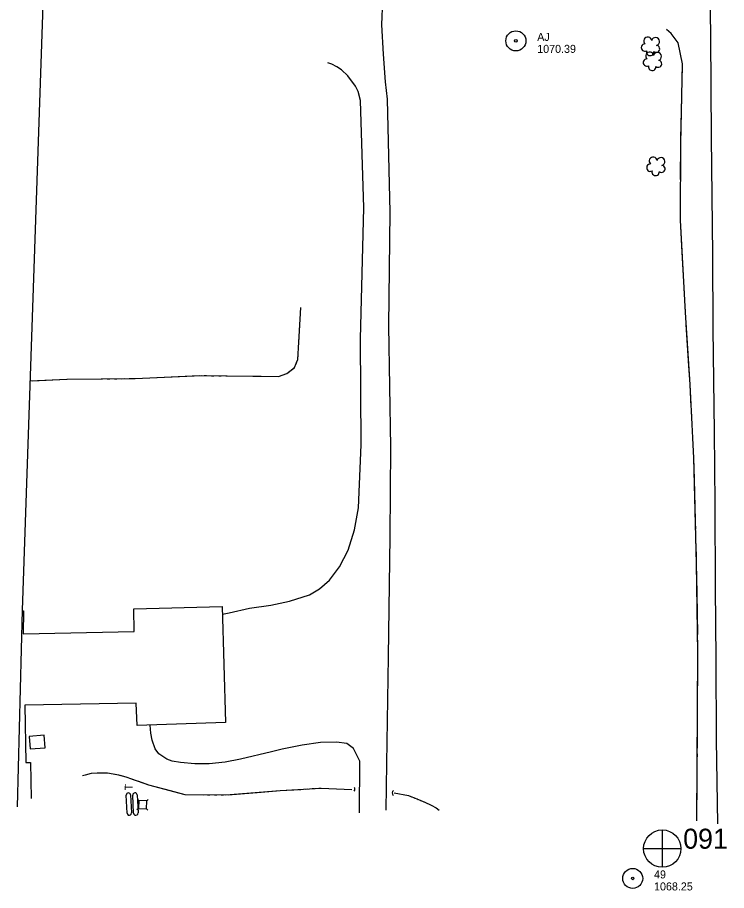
# Model space of a CAD drawing. Extents: x 296471 to 298892, y 33801 to 34997.
# Drawn here: x 297188 to 297719, y 33801 to 34456 of the extents above; entities that cross this region are included whole.
import ezdxf

# ---------------------------------------------------------------- set-up
doc = ezdxf.new("R2010")
doc.units = 0
for name, color, linetype in [('Level 11', 7, 'Continuous'), ('Level 12', 7, 'Continuous'), ('Level 15', 7, 'Continuous'), ('Level 17', 7, 'Continuous'), ('Level 18', 7, 'Continuous'), ('Level 19', 7, 'Continuous'), ('Level 21', 7, 'Continuous'), ('Level 4', 7, 'Continuous'), ('Level 6', 7, 'Continuous')]:
    doc.layers.add(name, color=color, linetype=linetype)

msp = doc.modelspace()

# ---------------------------------------------------------------- linework, layer by layer
at = {"layer": 'Level 11'}
msp.add_lwpolyline([(297712.34, 33851.57), (297711.29, 33914.53), (297711.16, 33974.94), (297710.5, 34028.32), (297710.34, 34091.16), (297709.89, 34145.17), (297708.94, 34222.49), (297708.52, 34278.1), (297707.52, 34365.88), (297707.09, 34441.48), (297706.15, 34514.1), (297705.99, 34583.52), (297706.04, 34650.6), (297705.21, 34744.77), (297704.07, 34846.29), (297703.4, 34892.56)], dxfattribs=at)
at = {"layer": 'Level 12'}
for p, q in [((297269.85, 33859.52), (297269.23, 33873)), ((297272.52, 33873.16), (297273.15, 33859.67)), ((297274.79, 33859.54), (297274.11, 33873.02)), ((297277.41, 33873.18), (297278.08, 33859.7))]:
    msp.add_line(p, q, dxfattribs=at)
msp.add_lwpolyline([(297191.45, 34010.98), (297192.17, 34010.99), (297191.98, 33993.78), (297275.08, 33995.65), (297274.91, 34012.55), (297341.1, 34014.31), (297343.57, 33927.3), (297277.49, 33925.17), (297276.7, 33941.96), (297193.2, 33940.31), (297194.15, 33897.46), (297197.55, 33897.48), (297198.05, 33870.37)], dxfattribs=at)
msp.add_lwpolyline([(297207.85, 33917.89), (297196.61, 33917.04), (297197.33, 33907.58), (297208.56, 33908.43)], close=True, dxfattribs=at)
for centre, start, end in [((297270.88, 33873.02), 4.77906, 180.51857), ((297275.76, 33873.04), 4.97665, 180.71616), ((297271.5, 33859.54), 180.68714, 4.64522), ((297276.44, 33859.56), 180.88472, 4.8428)]:
    msp.add_arc(centre, 1.65, start, end, dxfattribs=at)
at = {"layer": 'Level 15'}
for centre, radius, start, end in [((297438.91, 33877.41), 1.65, 306.22738, 52.46694), ((297470.65, 33874.53), 2.22, 123.89797, 230.13753)]:
    msp.add_arc(centre, radius, start, end, dxfattribs=at)
at = {"layer": 'Level 17'}
for points in [[(297461.14, 34468.65), (297460.39, 34450.19), (297461.79, 34428.23), (297463.08, 34407.37), (297464.7, 34394.53), (297466.63, 34309.8), (297465.6, 34224.54), (297467.09, 34133.77), (297466.72, 34066.77), (297465.52, 33976.61), (297464.25, 33896.65), (297463.74, 33861.65)], [(297341.27, 34008.5), (297346.31, 34009.68), (297361.67, 34013.16), (297377.54, 34015.44), (297391.62, 34018.36), (297406.49, 34023.18), (297413.97, 34027.48), (297421.38, 34034.02), (297429.05, 34043.95), (297435.54, 34056.51), (297440.26, 34071.8), (297443.29, 34088.35), (297445.25, 34135.42), (297444.67, 34214.88), (297447.08, 34313.11), (297444.81, 34393.56), (297442.97, 34400.29), (297440.95, 34404.28), (297435.3, 34411.94), (297430.49, 34416.43), (297426.99, 34418.84), (297423.29, 34420.62), (297420.33, 34421.65)], [(297443.99, 33859.76), (297444.14, 33898.54), (297439.35, 33907.9), (297434.42, 33911.77), (297426.61, 33912.73), (297414.75, 33912.33), (297400.89, 33910.31), (297385.92, 33907.49), (297377.97, 33905.41), (297354.81, 33899.93), (297343.43, 33897.69), (297331.4, 33896.55), (297320.51, 33896.47), (297309.89, 33897.32), (297303.75, 33898.46), (297299.71, 33900.04), (297293.66, 33903.97), (297290.83, 33907.61), (297288.58, 33914.19), (297287.67, 33919.3), (297287.19, 33925.44), (297287.19, 33925.48)]]:
    msp.add_lwpolyline(points, dxfattribs=at)
at = {"layer": 'Level 18'}
for centre, radius, start, end in [((297659.87, 34438.07), 2.97, 5.93972, 227.1736), ((297665.72, 34437.71), 2.97, 283.59054, 166.56381), ((297657.8, 34433.11), 2.78, 88.91061, 296.6836), ((297666.24, 34432.21), 2.61, 228.29577, 86.22838), ((297661.35, 34426.85), 2.97, 5.93972, 227.1736), ((297661.74, 34429.94), 2.78, 165.58763, 6.59867), ((297667.19, 34426.49), 2.97, 283.59054, 166.56381), ((297659.27, 34421.9), 2.78, 88.91061, 296.6836), ((297663.21, 34418.72), 2.78, 165.58763, 6.59867), ((297667.72, 34420.99), 2.61, 228.29577, 86.22838), ((297663.92, 34348.13), 2.97, 5.93972, 227.1736), ((297669.76, 34347.76), 2.97, 283.59054, 166.56381), ((297661.85, 34343.17), 2.78, 88.91061, 296.6836), ((297665.79, 34340), 2.78, 165.58763, 6.59867), ((297670.29, 34342.27), 2.61, 228.29577, 86.22838)]:
    msp.add_arc(centre, radius, start, end, dxfattribs=at)
at = {"layer": 'Level 19'}
for points in [[(297696.71, 33853.84), (297697.51, 33979.39), (297696.5, 34046.56), (297694.51, 34125.75), (297691.62, 34180.75), (297688.2, 34234.6), (297684.29, 34303.83), (297684.63, 34361.4), (297685.91, 34421.09), (297682.57, 34436.74), (297677.41, 34443.74), (297673.97, 34446.71)], [(297685.87, 34419.43), (297685.91, 34421.09), (297682.57, 34436.74), (297677.41, 34443.74), (297673.97, 34446.71)], [(297685.73, 34413.04), (297685.78, 34415.17)], [(297685.6, 34406.64), (297685.64, 34408.77)], [(297685.46, 34400.25), (297685.51, 34402.38)], [(297684.71, 34365.09), (297685.37, 34395.99)], [(297684.47, 34334.18), (297684.63, 34361.4), (297684.71, 34365.09)], [(297684.43, 34327.79), (297684.45, 34329.92)], [(297684.4, 34321.39), (297684.41, 34323.52)], [(297684.36, 34315), (297684.37, 34317.13)], [(297685.64, 34279.86), (297684.29, 34303.83), (297684.33, 34310.73)], [(297687.38, 34249), (297685.64, 34279.86)], [(297687.74, 34242.62), (297687.62, 34244.75)], [(297197.32, 34183.43), (297224.8, 34184.58), (297275.94, 34185.16), (297325.61, 34187.38), (297383.26, 34186.74), (297389.53, 34188.83), (297395.32, 34193.43), (297397.8, 34199.44), (297399.92, 34238.46)], [(297398.49, 34212.18), (297399.92, 34238.46)], [(297688.1, 34236.23), (297687.98, 34238.36)], [(297688.5, 34229.85), (297688.36, 34231.98)], [(297690.73, 34194.75), (297688.77, 34225.6)], [(297397.9, 34201.31), (297398, 34203.12)], [(297398.2, 34206.74), (297398.29, 34208.56)], [(297396.43, 34196.14), (297397.13, 34197.81)], [(297370.24, 34186.89), (297383.26, 34186.74), (297389.53, 34188.83), (297394.77, 34192.99)], [(297692.51, 34163.9), (297691.62, 34180.75), (297690.73, 34194.75)], [(297198.81, 34183.49), (297224.8, 34184.58), (297225.1, 34184.59)], [(297225.1, 34184.59), (297251.42, 34184.89)], [(297255.05, 34184.93), (297256.86, 34184.95)], [(297260.49, 34184.99), (297262.31, 34185.01)], [(297265.94, 34185.05), (297267.75, 34185.07)], [(297271.38, 34185.11), (297275.94, 34185.16), (297297.67, 34186.14)], [(297297.67, 34186.14), (297323.97, 34187.31)], [(297327.59, 34187.36), (297329.41, 34187.34)], [(297333.04, 34187.3), (297334.85, 34187.28)], [(297338.48, 34187.24), (297340.3, 34187.22)], [(297343.93, 34187.18), (297370.24, 34186.89)], [(297692.84, 34157.51), (297692.73, 34159.64)], [(297693.18, 34151.12), (297693.06, 34153.25)], [(297693.51, 34144.74), (297693.4, 34146.87)], [(297694.91, 34109.6), (297694.51, 34125.75), (297693.73, 34140.48)], [(297695.69, 34078.7), (297694.91, 34109.6)], [(297695.85, 34072.31), (297695.8, 34074.44)], [(297696.01, 34065.92), (297695.96, 34068.05)], [(297696.17, 34059.52), (297696.12, 34061.65)], [(297696.84, 34024.36), (297696.5, 34046.56), (297696.28, 34055.26)], [(297697.3, 33993.46), (297696.84, 34024.36)], [(297697.4, 33987.06), (297697.37, 33989.19)], [(297697.49, 33980.67), (297697.46, 33982.8)], [(297697.48, 33974.27), (297697.49, 33976.4)], [(297697.26, 33939.1), (297697.45, 33970.01)], [(297697.06, 33908.2), (297697.26, 33939.1)], [(297697.02, 33901.8), (297697.03, 33903.93)], [(297696.98, 33895.41), (297696.99, 33897.54)], [(297438.28, 33877.01), (297415.13, 33878.02), (297384.53, 33876.12), (297343.84, 33872.89), (297313.43, 33873.2), (297286.1, 33880.54), (297269.28, 33886.4), (297263.74, 33887.93), (297255.13, 33889.42), (297247.35, 33889.49), (297242.97, 33889.13), (297238.42, 33888.05), (297236.38, 33887.54)], [(297260.8, 33888.44), (297255.13, 33889.42), (297247.35, 33889.49), (297242.97, 33889.13), (297238.42, 33888.05), (297236.38, 33887.54)], [(297696.93, 33889.01), (297696.95, 33891.14)], [(297265.79, 33887.36), (297264.15, 33887.82)], [(297270.69, 33885.9), (297269.28, 33886.4), (297269.08, 33886.45)], [(297275.52, 33884.22), (297273.91, 33884.78)], [(297302.46, 33876.15), (297286.1, 33880.54), (297278.74, 33883.1)], [(297696.71, 33853.84), (297696.91, 33884.75)], [(297326.79, 33873.07), (297313.43, 33873.2), (297302.46, 33876.15)], [(297394.85, 33876.76), (297384.53, 33876.12), (297370.19, 33874.98)], [(297399.96, 33877.07), (297398.26, 33876.97)], [(297405.07, 33877.39), (297403.36, 33877.29)], [(297410.17, 33877.71), (297408.47, 33877.6)], [(297438.28, 33877.01), (297415.13, 33878.02), (297413.58, 33877.92)], [(297331.91, 33873.01), (297330.2, 33873.03)], [(297337.02, 33872.96), (297335.32, 33872.98)], [(297342.14, 33872.91), (297340.43, 33872.93)], [(297370.19, 33874.98), (297345.54, 33873.03)], [(297470.05, 33874.64), (297480.54, 33872.69), (297488.06, 33869.77), (297492.97, 33867.64), (297497.62, 33865.52), (297501.46, 33863.45), (297503.62, 33861.71)], [(297470.05, 33874.64), (297480.54, 33872.69), (297482.87, 33871.79)], [(297484.57, 33871.13), (297485.41, 33870.8)], [(297487.11, 33870.14), (297487.95, 33869.81)], [(297489.62, 33869.09), (297490.45, 33868.73)], [(297492.12, 33868.01), (297492.97, 33867.64), (297497.62, 33865.52), (297501.46, 33863.45), (297503.62, 33861.71)]]:
    msp.add_lwpolyline(points, dxfattribs=at)
at = {"layer": 'Level 21'}
for p, q in [((297278.62, 33868.97), (297277.61, 33870.08)), ((297285.72, 33869.73), (297284.62, 33868.71)), ((297278.36, 33862.98), (297277.26, 33861.97)), ((297285.37, 33861.61), (297284.36, 33862.72))]:
    msp.add_line(p, q, dxfattribs=at)
msp.add_lwpolyline([(297284.36, 33862.72), (297284.62, 33868.71), (297278.62, 33868.97), (297278.36, 33862.98)], close=True, dxfattribs=at)
at = {"layer": 'Level 4'}
for p, q in [((297670.69, 33846.93), (297670.63, 33819.08)), ((297656.78, 33832.9), (297684.69, 33832.89))]:
    msp.add_line(p, q, dxfattribs=at)
msp.add_lwpolyline([(297187.76, 33864.29), (297191.46, 34011.67), (297222.13, 34911.46)], dxfattribs=at)
msp.add_circle((297670.74, 33832.91), 14, dxfattribs=at)
at = {"layer": 'Level 6'}
for centre, radius in [((297561.08, 34438.18), 7.5), ((297561.08, 34438.18), 0.96), ((297648.59, 33810.58), 7.5), ((297648.59, 33810.58), 0.96)]:
    msp.add_circle(centre, radius, dxfattribs=at)

# ---------------------------------------------------------------- texts
at = {"layer": 'Level 12'}
msp.add_text('T', height=6, rotation=87.51606, dxfattribs=at).set_placement((297274.04, 33876.4))
at = {"layer": 'Level 4'}
msp.add_text('091', height=15, dxfattribs=at).set_placement((297686.4, 33832.84))
at = {"layer": 'Level 6'}
for s, p in [('AJ', (297577.08, 34438.18)), ('1070.39', (297577.08, 34429.18)), ('49', (297664.59, 33810.58)), ('1068.25', (297664.59, 33801.58))]:
    msp.add_text(s, height=6, dxfattribs=at).set_placement(p)

doc.saveas('drawing.dxf')
